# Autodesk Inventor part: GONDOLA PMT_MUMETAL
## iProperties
Shininess: 64.0
Length Units: 11272
Angle Units: 11279
Time Units: 11290
Mass Units: 11286
Length Display Precision: 3
Angle Display Precision: 2
Compacted: True
Part Number: GONDOLA PMT_MUMETAL
Document SubType Name: Modeling
Created: 2004-08
Designer: John Blackburn
Manufacturer: Standard
Standards Organization: Custom
Material: Steel, Mild
Density: 0.0
Volumn: 0.0
Area: 0.0
PropertySet Name: Model Information
Control State: 0
Master: False
Checked Out: False
Author: John Blackburn
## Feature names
1. Base1
